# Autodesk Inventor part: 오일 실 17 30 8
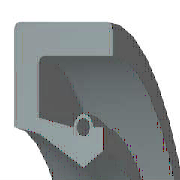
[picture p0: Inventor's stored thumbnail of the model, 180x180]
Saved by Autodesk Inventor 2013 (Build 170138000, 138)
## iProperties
Created: 2012-02
Part Number: 오일 실 17 30 8
Material: 고무
Description: 오일-실
Document SubType Name: Modeling
Standard: KS B 2804
Designer: mduedu
Standards Organization: KS
Language: ko-KR
Size Designation: S - 17 30 8
Categories: <MemberInstance><Categories><Category DisplayName="샤프트 부품" InternalName="7f7aeb1f-a693-4053-b835-cee3144e0d98" Mnemonic="SHFT"><Category DisplayName="실링" Intern
Density: 0.93 g/cm^3
IsCustomPart: 1
Author: mduedu
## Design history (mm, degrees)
revolve "본체" stored, may be unused: angle "d17" = 90 deg
revolve "스프링1" stored, may be unused: angle "d18" = 90 deg
body "Solid1"
sketch "스케치1"
  geometry: L1 (0, 15)-(8, 15); L2 (8, 15)-(8, 13.75); L3 (8, 13.75)-(1.75, 13.75); L4 (0, 15)-(0, 10.6); L5 (0, 10.6)-(1.75, 10.25); L6 (1.75, 10.25)-(4.9, 8.5); L7 (4.9, 8.5)-(0, 8.5); L8 (6.3, 9.375)-(6.3, 10.6); L9 (0, 0)-(9.586, 0) reference; L10 (4.9, 8.5)-(6.3, 9.375); L11 (0, 18)-(0, -3) reference; L12 (-1.917, 0)-(11.503, 0) reference; L13 (4.2, 10.6)-(1.75, 11.09); L14 (1.75, 11.09)-(1.75, 13.75); L15 (6.3, 10.6)-(5.6, 10.6); C1 r 0.455 at (4.9, 10.6); A1 r 0.7 centre (4.9, 10.6) between (5.6, 10.6) and (4.2, 10.6)
  constraints: 26 end point, 5 horizontal alignment, 4 perpendicular, 2 centre point, 2 collinear, 2 horizontal, 2 parallel, 2 point on circle, 2 point on line, 2 vertical alignment, 1 coincident
  dimensions: "d0" = 30 diameter of L1 L9 (= SD2); "d1" = 18.75 diameter of L8.start L9 (= ABDM); "d2" = 1.25 distance of L1.end L2.end (computed from SD); "d3" = 0.91 diameter of C1 (= SPDI); "d4" = 1.4 diameter of A1 (= SPDA); "d5" = 17 diameter of L6.end L9 (= NND); "d6" = 20.5 diameter of L5.end L9 (= TKDM); "d7" = 21.2 diameter of L4.end L9 (= HLDM); "d8" = 4.9 distance from line of C1.centre L4 (= SPDST); "d9" = 6.3 distance between parallel lines of L8 L4 (= SDI); "d10" = 8 distance between parallel lines of L2 L4 (= SWDT); "d12" = 1.75 distance between parallel lines of L14 L4 (= SD)
fillet "모깎기1" dims "d11" = 0.3 (= RR)
other parameters: "SD2" = 30 [user parameter; used in 1 equation term], "SWDT" = 8 [user parameter; used in 1 equation term], "RR" = 0.3 [user parameter; used in 1 equation term], "SD" = 1.75 [user parameter; used in 2 equation terms], "NND" = 17 [user parameter; used in 1 equation term], "SPDA" = 1.4 [user parameter; used in 1 equation term], "SPDI" = 0.91 [user parameter; used in 1 equation term], "TKDM" = 20.5 [user parameter; used in 1 equation term], "HLDM" = 21.2 [user parameter; used in 1 equation term], "ABDM" = 18.75 [user parameter; used in 1 equation term], "SDI" = 6.3 [user parameter; used in 1 equation term], "SPDST" = 4.9 [user parameter; used in 1 equation term], "d13" = 0, "d14" = 0, "d15" = 0, "LAB" = 0.35 [user parameter]
